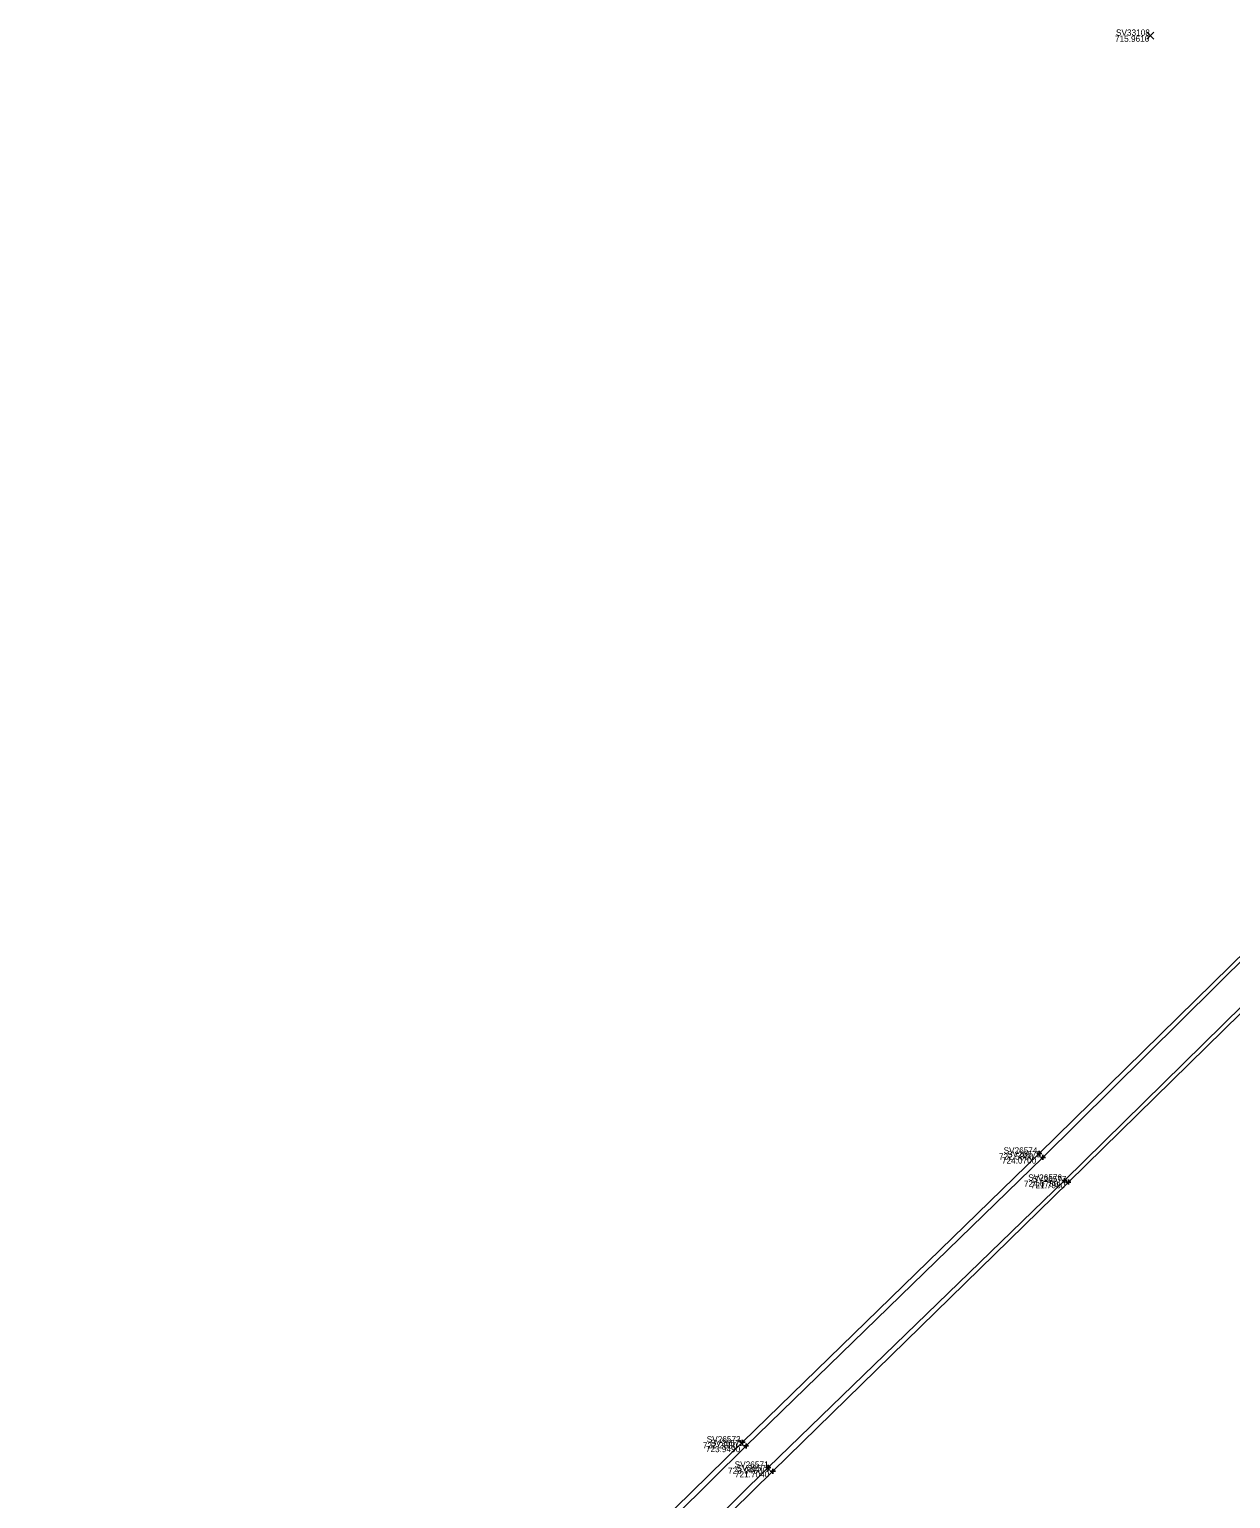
# Model space of a CAD drawing. Extents: x 182090 to 1832865, y 706265 to 714392.
# Drawn here: x 1825003 to 1825061.5, y 712237.7 to 712309.3 of the extents above; entities that cross this region are included whole.
import ezdxf

# ---------------------------------------------------------------- set-up
doc = ezdxf.new("R2010")
doc.units = 0
for name, color, linetype in [('PV_X_EOP', 7, 'Continuous'), ('RD_X_Wall', 7, 'Continuous'), ('SV_X_Break_Lines', 7, 'Continuous'), ('SV_X_Random_Point', 7, 'Continuous'), ('SV_X_Shot_Marker', 7, 'Continuous'), ('SV_X_Text_Elevation', 7, 'Continuous'), ('SV_X_Text_Name', 7, 'Continuous')]:
    doc.layers.add(name, color=color, linetype=linetype)

msp = doc.modelspace()

# ---------------------------------------------------------------- linework, layer by layer
at = {"layer": 'PV_X_EOP'}
msp.add_lwpolyline([(1825005.534, 712208.507), (1825007.925, 712211.228), (1825022.12, 712225.163), (1825037.737, 712240.479), (1825052.182, 712254.544), (1825065.694, 712267.794), (1825069.94, 712272.139)], dxfattribs=at)
at = {"layer": 'RD_X_Wall'}
for points in [[(1824873.746, 712069.025), (1824889.903, 712087.578), (1824891.904, 712090.011), (1824904.728, 712102.902), (1824922.701, 712120.868), (1824940.461, 712138.54), (1824958.046, 712156.189), (1824974.939, 712173.164), (1824976.739, 712175.003), (1824987.136, 712171.976), (1824988.648, 712171.661), (1825012.23, 712194.877), (1825007.48, 712208.135), (1825009.225, 712209.991), (1825023.339, 712223.79), (1825038.991, 712239.251), (1825053.401, 712253.223), (1825066.927, 712266.513), (1825071.264, 712270.82), (1825079.453, 712274.725), (1825095.866, 712282.375), (1825122.849, 712295.182), (1825131.958, 712299.575), (1825131.307, 712300.869)], [(1824872.663, 712069.995), (1824888.683, 712088.577), (1824890.837, 712091.041), (1824903.726, 712104.018), (1824921.17, 712121.459), (1824921.667, 712121.895), (1824939.345, 712139.647), (1824956.945, 712157.295), (1824973.864, 712174.19), (1824976.173, 712176.691), (1824988.279, 712173.102), (1825003.981, 712188.77), (1825010.605, 712195.266), (1825005.926, 712208.474), (1825008.09, 712210.984), (1825022.371, 712224.907), (1825037.911, 712240.3), (1825052.357, 712254.351), (1825065.818, 712267.68)]]:
    msp.add_lwpolyline(points, dxfattribs=at)
at = {"layer": 'SV_X_Break_Lines'}
msp.add_lwpolyline([(1825023.486, 712223.606), (1825039.214, 712239.069), (1825053.595, 712253.15), (1825067.026, 712266.305), (1825071.452, 712270.621), (1825071.515, 712270.716), (1825079.392, 712274.371), (1825095.974, 712282.158), (1825122.955, 712294.792), (1825132.488, 712299.302), (1825131.485, 712301.271), (1825130.098, 712300.699)], dxfattribs=at)
at = {"layer": 'SV_X_Random_Point'}
for p, q in [((1825057.416, 712308.8), (1825057.75, 712309.134)), ((1825057.416, 712309.134), (1825057.75, 712308.8))]:
    msp.add_line(p, q, dxfattribs=at)
at = {"layer": 'SV_X_Shot_Marker'}
for p, q in [((1825052.057, 712254.544), (1825052.307, 712254.544)), ((1825052.182, 712254.669), (1825052.182, 712254.419)), ((1825052.182, 712254.544), (1825052.182, 712254.544)), ((1825052.232, 712254.351), (1825052.482, 712254.351)), ((1825052.357, 712254.476), (1825052.357, 712254.226)), ((1825052.357, 712254.351), (1825052.357, 712254.351)), ((1825053.276, 712253.223), (1825053.526, 712253.223)), ((1825053.401, 712253.348), (1825053.401, 712253.098)), ((1825053.401, 712253.223), (1825053.401, 712253.223)), ((1825053.47, 712253.15), (1825053.72, 712253.15)), ((1825053.595, 712253.275), (1825053.595, 712253.025)), ((1825053.595, 712253.15), (1825053.595, 712253.15)), ((1825037.737, 712240.604), (1825037.737, 712240.354)), ((1825037.612, 712240.479), (1825037.862, 712240.479)), ((1825037.737, 712240.479), (1825037.737, 712240.479)), ((1825037.786, 712240.3), (1825038.036, 712240.3)), ((1825037.911, 712240.425), (1825037.911, 712240.175)), ((1825037.911, 712240.3), (1825037.911, 712240.3)), ((1825038.866, 712239.251), (1825039.116, 712239.251)), ((1825038.991, 712239.376), (1825038.991, 712239.126)), ((1825038.991, 712239.251), (1825038.991, 712239.251)), ((1825039.214, 712239.194), (1825039.214, 712238.944)), ((1825039.089, 712239.069), (1825039.339, 712239.069)), ((1825039.214, 712239.069), (1825039.214, 712239.069))]:
    msp.add_line(p, q, dxfattribs=at)

# ---------------------------------------------------------------- texts
at = {"layer": 'SV_X_Text_Elevation'}
for s, p in [('715.9610', (1825055.864, 712308.667)), ('722.5800', (1825050.217, 712254.244)), ('724.0700', (1825050.361, 712254.051)), ('724.0780', (1825051.433, 712252.923)), ('721.7980', (1825051.772, 712252.85)), ('722.2880', (1825035.805, 712240.179)), ('723.9490', (1825035.953, 712240)), ('723.9460', (1825037.033, 712238.951)), ('721.7040', (1825037.365, 712238.769))]:
    msp.add_text(s, height=0.3, dxfattribs=at).set_placement(p)
at = {"layer": 'SV_X_Text_Name'}
for s, p in [('SV33108', (1825055.913, 712308.967)), ('SV26574', (1825050.441, 712254.544)), ('SV26575', (1825050.614, 712254.351)), ('SV26576', (1825051.639, 712253.223)), ('SV26577', (1825051.852, 712253.15)), ('SV26573', (1825035.994, 712240.479)), ('SV26572', (1825036.17, 712240.3)), ('SV26571', (1825037.357, 712239.251)), ('SV26570', (1825037.445, 712239.069))]:
    msp.add_text(s, height=0.3, dxfattribs=at).set_placement(p)

doc.saveas('drawing.dxf')
